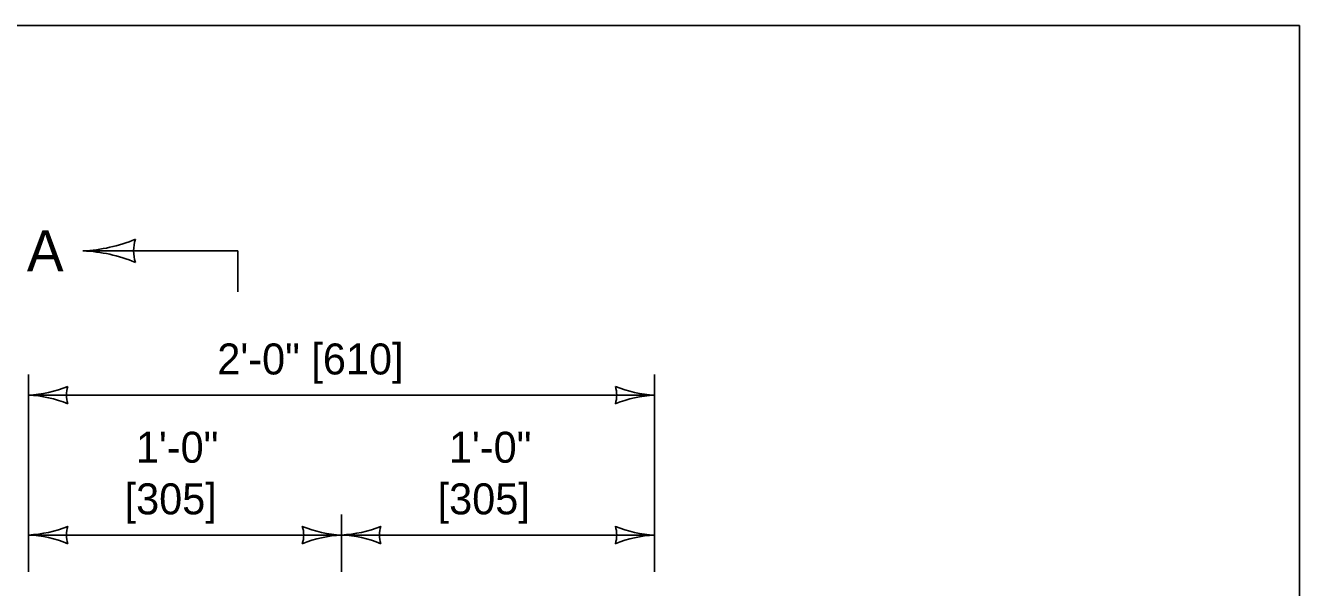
# Model space of a CAD drawing. Extents: x 49991.4 to 50021, y 49987.6 to 50011.4.
# Drawn here: x 50006.148 to 50008.615, y 50010.174 to 50011.263 of the extents above; entities that cross this region are included whole.
import ezdxf

# ---------------------------------------------------------------- set-up
doc = ezdxf.new("R2010")
doc.units = 0
for name, color, linetype in [('Level 1', 7, 'Continuous'), ('Level 2', 7, 'Continuous'), ('Level 3', 7, 'Continuous'), ('Level 6', 7, 'Continuous')]:
    doc.layers.add(name, color=color, linetype=linetype)

msp = doc.modelspace()

# ---------------------------------------------------------------- linework, layer by layer
at = {"layer": 'Level 1'}
msp.add_lwpolyline([(50008.6146, 50011.2628), (50000.3356, 50011.2628), (50000.3356, 50000.0624), (50008.6146, 50000.0624)], close=True, dxfattribs=at)
at = {"layer": 'Level 3'}
for p, q in [((50006.1541, 50010.2048), (50006.1541, 50010.5869)), ((50007.3661, 50010.2048), (50007.3661, 50010.5869)), ((50006.1541, 50010.5469), (50007.3661, 50010.5469)), ((50006.7601, 50010.2048), (50006.7601, 50010.3159)), ((50006.1541, 50010.2759), (50006.7601, 50010.2759)), ((50006.7601, 50010.2759), (50007.3661, 50010.2759))]:
    msp.add_line(p, q, dxfattribs=at)
for centre, radius, start, end in [((50006.2441, 50011.1365), 0.3107, 272.8273, 292.0772), ((50006.4304, 50010.8263), 0.073, 162.1388, 197.8612), ((50006.2472, 50010.5301), 0.2964, 67.456, 87.6395), ((50006.1426, 50010.7796), 0.233, 272.8273, 292.0772), ((50006.2823, 50010.5469), 0.0548, 162.1388, 197.8612), ((50007.3753, 50010.769), 0.2223, 247.456, 267.6395), ((50007.2379, 50010.5469), 0.0548, 342.1388, 17.8612), ((50006.1449, 50010.3247), 0.2223, 67.456, 87.6395), ((50007.3776, 50010.3142), 0.233, 92.8273, 112.0772), ((50006.1426, 50010.5086), 0.233, 272.8273, 292.0772), ((50006.2823, 50010.2759), 0.0548, 162.1388, 197.8612), ((50006.7693, 50010.498), 0.2223, 247.456, 267.6395), ((50006.6319, 50010.2759), 0.0548, 342.1388, 17.8612), ((50006.7486, 50010.5086), 0.233, 272.8273, 292.0772), ((50006.8883, 50010.2759), 0.0548, 162.1388, 197.8612), ((50007.3753, 50010.498), 0.2223, 247.456, 267.6395), ((50007.2379, 50010.2759), 0.0548, 342.1388, 17.8612), ((50006.1449, 50010.0538), 0.2223, 67.456, 87.6395), ((50006.7716, 50010.0432), 0.233, 92.8273, 112.0772), ((50006.7509, 50010.0538), 0.2223, 67.456, 87.6395), ((50007.3776, 50010.0432), 0.233, 92.8273, 112.0772)]:
    msp.add_arc(centre, radius, start, end, dxfattribs=at)
at = {"layer": 'Level 6'}
for p, q in [((50006.2594, 50010.8263), (50006.5589, 50010.8263)), ((50006.5589, 50010.8263), (50006.5589, 50010.7469))]:
    msp.add_line(p, q, dxfattribs=at)

# ---------------------------------------------------------------- texts
at = {"layer": 'Level 2'}
for s, height, p in [('A', 0.08, (50006.1507, 50010.7863)), ('2\'-0" [610]', 0.06, (50006.5195, 50010.5869)), ('1\'-0"', 0.06, (50006.3618, 50010.4159)), ('1\'-0"', 0.06, (50006.9678, 50010.4159)), ('[305]', 0.06, (50006.34, 50010.3159)), ('[305]', 0.06, (50006.946, 50010.3159))]:
    msp.add_text(s, height=height, dxfattribs=at).set_placement(p)

doc.saveas('drawing.dxf')
